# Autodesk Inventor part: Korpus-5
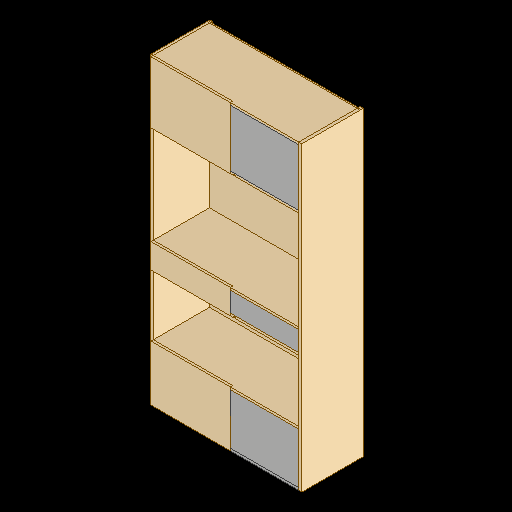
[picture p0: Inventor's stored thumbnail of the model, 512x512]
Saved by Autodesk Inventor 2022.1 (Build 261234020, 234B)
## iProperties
Created: 2021-09
Part Number: Korpus-5
Material: Generisch
Document SubType Name: Modeling
Designer: J. Ruhl
Density: 1 g/cm^3
Appearance: Vorgabe
Author: J. Ruhl
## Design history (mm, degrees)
sketch "Skizze11"
  geometry: L1 (0, 0)-(19, 0); L2 (19, 0)-(19, 500); L3 (19, 500)-(0, 500); L4 (0, 500)-(0, 0); L5 (1219, 0)-(1244, 0); L6 (1244, 0)-(1244, 500); L7 (1244, 500)-(1219, 500); L8 (1219, 500)-(1219, 0); L9 (19, 0)-(663, 0); L10 (663, 0)-(663, 19); L11 (663, 19)-(19, 19); L12 (19, 19)-(19, 0); L13 (9, 485)-(1229, 485); L14 (1229, 485)-(1229, 475); L15 (1229, 475)-(9, 475); L16 (9, 475)-(9, 485); L17 (10, 485)-(10, 475); L18 (1228, 485)-(1228, 475); L19 (663, 0)-(1219, 0); L20 (19, 19)-(0, 19); 7 further points
  constraints: 40 end point, 8 parallel, 6 horizontal, 4 perpendicular, 4 point on line, 2 collinear, 2 vertical
  dimensions: "d132" = 19 distance of L3.end L2.end; "d133" = 500 distance of L2.end L1.end; "d134" = 25 distance of L7.end L6.end; "d135" = 1244 distance between parallel lines of L6 L4; "d136" = 644 distance of L11.end L10.end; "d137" = 19 distance of L10.end L9.end; "d138" = 10 distance of L13.end L14.end; "d139" = 15 distance between parallel lines of L13 L7; "d140" = 10 distance between parallel lines of L8 L14; "d141" = 10 distance between parallel lines of L2 L16; "d142" = 1 distance between parallel lines of L16 L17; "d143" = 1 distance between parallel lines of L14 L18; "d231" = 19 distance of L11.end L20.end; "d232" = 0 vertical distance of L11.end L20.end (derived)
extrude "Extrusion18" new body sketch "Skizze11" distance "d144" = 2450; taper "d145" = 0 deg
extrude "Extrusion19" new body sketch "Skizze11" stored distance "d146" = 1950; taper "d147" = 0 deg
extrude "Extrusion20" new body sketch "Skizze11" distance "d148" = 19; taper "d149" = 0 deg
extrude "Extrusion21" new body sketch "Skizze11" stored distance "d150" = 1950; taper "d151" = 0 deg
extrude "Extrusion22" new body sketch "Skizze11" distance "d152" = 450; taper "d153" = 0 deg
pattern_linear "Rechteckige Anordnung3" dims "d156" = 431
pattern_linear "Rechteckige Anordnung4" dims "d159" = 519
pattern_linear "Rechteckige Anordnung5" dims "d162" = 181
extrude "Extrusion23" new body sketch "Skizze11" stored distance "d163" = 400; taper "d164" = 0 deg
sketch "Skizze12"
  geometry: L1 (-19, 19)-(-663, 19) reference; L2 (-19, 475)-(-19, 19) reference; C1 r 5 at (-40, 47); C2 r 5 at (-40, 111); C3 r 5 at (-104, 47); C4 r 5 at (-104, 111); 1 further point
  constraints: 4 centre point, 2 horizontal alignment, 2 vertical alignment
  dimensions: "d165" = 10 diameter of C1; "d166" = 10 diameter of C2; "d167" = 10 diameter of C3; "d168" = 10 diameter of C4; "d169" = 28 distance from line of L1 C3.centre; "d170" = 21 distance from line of L2 C2.centre; "d173" = 64 distance of C4.centre C3.centre; "d174" = 64 distance of C4.centre C2.centre
extrude "Extrusion24" cut sketch "Skizze12" distance "d171" = 11; taper "d172" = 0 deg
pattern_linear "Rechteckige Anordnung6" dims "d177" = 1094, "d180" = 340
pattern_linear "Rechteckige Anordnung7"
pattern_linear "Rechteckige Anordnung8" dims "d186" = 481
extrude "Extrusion25" new body sketch "Skizze11" stored distance "d187" = 10; taper "d188" = 0 deg
sketch "Skizze13"
  geometry: L1 (2431, 0)-(2431, 475) reference; L2 (1969, 0)-(1969, 475) reference; L3 (1950, 0)-(1950, 475) reference; L4 (1150, 0)-(1150, 475) reference; L5 (1131, 0)-(1131, 475) reference; L6 (969, 0)-(969, 475) reference; L7 (950, 0)-(950, 475) reference; L8 (450, 0)-(450, 475) reference; L9 (431, 0)-(431, 475) reference; L10 (19, 0)-(19, 475) reference; L11 (0, 0)-(19, 0) reference; L12 (19, 0)-(431, 0); L13 (431, 0)-(431, 19); L14 (431, 19)-(19, 19); L15 (19, 19)-(19, 0); L16 (950, 0)-(969, 0) reference; L17 (969, 0)-(1131, 0); L18 (1131, 0)-(1131, 19); L19 (1131, 19)-(969, 19); L20 (969, 19)-(969, 0); L21 (1969, 0)-(2431, 0); L22 (2431, 0)-(2431, 19); L23 (2431, 19)-(1969, 19); L24 (1969, 19)-(1969, 0)
  constraints: 24 end point, 6 parallel, 3 collinear, 3 horizontal, 3 perpendicular
  dimensions: "d189" = 19 distance of L13.end L12.end; "d190" = 19 distance of L18.end L17.end; "d191" = 19 distance of L22.end L21.end
extrude "Extrusion26" new body sketch "Skizze13" stored distance "d192" = 600; taper "d193" = 0 deg
extrude "Extrusion27" new body sketch "Skizze13" stored distance "d194" = 10; taper "d195" = 0 deg
extrude "Extrusion28" new body sketch "Skizze13" stored distance "d196" = 10; taper "d197" = 0 deg
sketch "Skizze15"
  geometry: L1 (556, -475)-(0, -475) reference; L2 (1200, 0)-(1200, -456) reference; L3 (1200, -425)-(511, -425); L4 (511, -425)-(511, -408); L5 (511, -408)-(1200, -408); L6 (1200, -408)-(1200, -425); L7 (556, -456)-(556, -475) reference; L8 (511, -408)-(528, -408); L9 (528, -408)-(528, -475); L10 (528, -475)-(511, -475); L11 (511, -475)-(511, -408); 3 further points
  constraints: 16 end point, 4 parallel, 2 collinear, 2 horizontal, 2 perpendicular
  dimensions: "d210" = 17 distance of L3.end L4.end; "d211" = 50 distance between parallel lines of L1 L3; "d229" = 17 distance of L9.end L10.end; "d230" = 28 distance between parallel lines of L7 L9
extrude "Extrusion30" cut sketch "Skizze15" distance "d212" = 9; taper "d213" = 0 deg
extrude "Extrusion32" cut sketch "Skizze15" stored distance "d221" = 9; taper "d222" = 0 deg
sketch "Skizze19"
  geometry: L1 (-1959, 48)-(-1959, 31) reference; L2 (-959, 48)-(-959, 31) reference; C1 r 5 at (-1954, 39.5); C2 r 5 at (-954, 39.5); 3 further points
  constraints: 2 centre point, 2 horizontal alignment, 2 midpoint
  dimensions: "d238" = 10 diameter of C1; "d239" = 5 distance from line of L1 C1.centre; "d240" = 10 diameter of C2; "d241" = 5 distance from line of C2.centre L2
extrude "Extrusion35" cut sketch "Skizze19" extent not by distance; stored distance "d242" = 0; taper "d243" = 0 deg
node "Volumenkörper13"
node "Volumenkörper14"
node "Volumenkörper15"
node "Volumenkörper16"
node "Volumenkörper17"
feature "Anordnung von Volumenkörper15:1"
node "Volumenkörper18"
feature "Anordnung von Volumenkörper18:2"
node "Volumenkörper19"
feature "Anordnung von Volumenkörper19:3"
node "Volumenkörper20"
node "Volumenkörper21"
feature "Anordnung von Volumenkörper20:4"
node "Volumenkörper22"
feature "Anordnung von Volumenkörper22:5"
node "Volumenkörper23"
node "Volumenkörper24"
node "Volumenkörper25"
node "Volumenkörper26"
node "Volumenkörper27"
